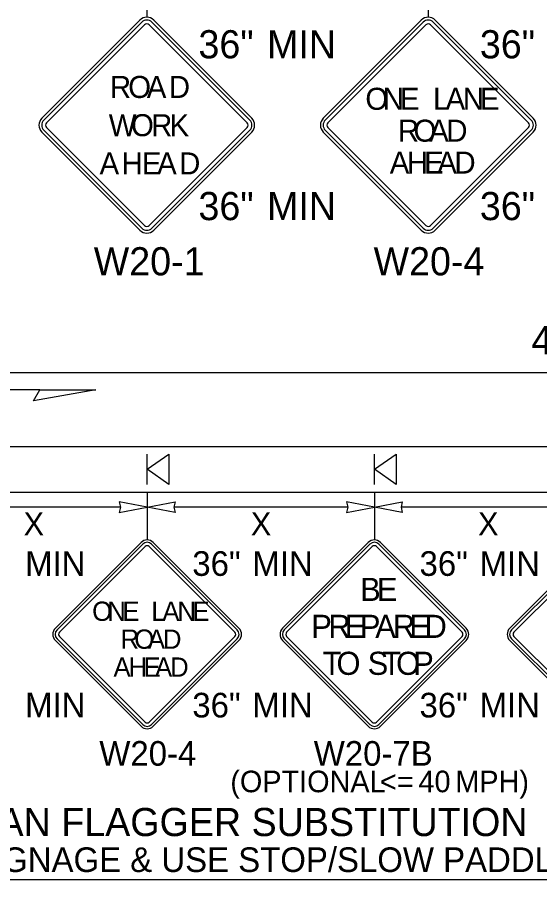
# Model space of a CAD drawing. Extents: x 99999.1 to 100095.7, y 99995 to 100010.7.
# Drawn here: x 100040.708 to 100042.194, y 100003.042 to 100005.492 of the extents above; entities that cross this region are included whole.
import ezdxf

# ---------------------------------------------------------------- set-up
doc = ezdxf.new("R2010")
doc.units = 0
for name, color, linetype in [('RD_ED_ShoulderPavedEdge', 7, 'Continuous'), ('RD_MK_LineEdgeWhite', 7, 'Continuous'), ('SH_DE_DetailHeading2Text', 7, 'Continuous'), ('TR_SN_ConstructionSigns', 7, 'Continuous'), ('TR_WZ_PortableSignMountBlk-Org', 7, 'Continuous'), ('TR_WZ_WorkZoneDetails', 7, 'Continuous'), ('TR_WZ_WorkZoneTextCurrent', 7, 'Continuous')]:
    doc.layers.add(name, color=color, linetype=linetype)

msp = doc.modelspace()

# ---------------------------------------------------------------- linework, layer by layer
at = {"layer": 'RD_ED_ShoulderPavedEdge'}
msp.add_line((100040.2089, 100004.1438), (100043.1825, 100004.1438), dxfattribs=at)
at = {"layer": 'RD_MK_LineEdgeWhite'}
msp.add_line((100040.2089, 100004.273), (100043.1825, 100004.273), dxfattribs=at)
at = {"layer": 'TR_SN_ConstructionSigns'}
for p, q in [((100041.0568, 100005.4841), (100040.7783, 100005.2057)), ((100041.0623, 100005.4786), (100040.7839, 100005.2001)), ((100040.7916, 100005.1924), (100041.07, 100005.4708)), ((100041.0833, 100005.4708), (100041.3617, 100005.1924)), ((100041.3694, 100005.2001), (100041.091, 100005.4786)), ((100041.375, 100005.2057), (100041.0965, 100005.4841)), ((100041.8568, 100005.4841), (100041.5783, 100005.2057)), ((100041.8623, 100005.4786), (100041.5839, 100005.2001)), ((100041.5916, 100005.1924), (100041.87, 100005.4708)), ((100041.8833, 100005.4708), (100042.1617, 100005.1924)), ((100042.1694, 100005.2001), (100041.891, 100005.4786)), ((100042.175, 100005.2057), (100041.8965, 100005.4841)), ((100040.7839, 100005.1714), (100041.0623, 100004.893)), ((100041.07, 100004.9007), (100040.7916, 100005.1792)), ((100041.3617, 100005.1792), (100041.0833, 100004.9007)), ((100041.091, 100004.893), (100041.3694, 100005.1714)), ((100041.5839, 100005.1714), (100041.8623, 100004.893)), ((100041.87, 100004.9007), (100041.5916, 100005.1792)), ((100042.1617, 100005.1792), (100041.8833, 100004.9007)), ((100041.891, 100004.893), (100042.1694, 100005.1714)), ((100040.7783, 100005.1659), (100041.0568, 100004.8875)), ((100041.0965, 100004.8875), (100041.375, 100005.1659)), ((100041.5783, 100005.1659), (100041.8568, 100004.8875)), ((100041.8965, 100004.8875), (100042.175, 100005.1659)), ((100041.0602, 100004.0005), (100040.8166, 100003.7569)), ((100041.065, 100003.9957), (100040.8214, 100003.752)), ((100041.3338, 100003.752), (100041.0902, 100003.9957)), ((100041.3386, 100003.7569), (100041.095, 100004.0005)), ((100041.7061, 100004.0005), (100041.4625, 100003.7569)), ((100041.711, 100003.9957), (100041.4673, 100003.752)), ((100041.9797, 100003.752), (100041.7361, 100003.9957)), ((100041.9846, 100003.7569), (100041.7409, 100004.0005)), ((100042.3521, 100004.0005), (100042.1084, 100003.7569)), ((100042.3569, 100003.9957), (100042.1133, 100003.752)), ((100040.8282, 100003.7453), (100041.0718, 100003.9889)), ((100041.0834, 100003.9889), (100041.327, 100003.7453)), ((100041.4741, 100003.7453), (100041.7177, 100003.9889)), ((100041.7293, 100003.9889), (100041.973, 100003.7453)), ((100042.12, 100003.7453), (100042.3637, 100003.9889)), ((100040.8214, 100003.7269), (100041.065, 100003.4833)), ((100041.0718, 100003.4901), (100040.8282, 100003.7337)), ((100041.327, 100003.7337), (100041.0834, 100003.4901)), ((100041.0902, 100003.4833), (100041.3338, 100003.7269)), ((100041.4673, 100003.7269), (100041.711, 100003.4833)), ((100041.7177, 100003.4901), (100041.4741, 100003.7337)), ((100041.973, 100003.7337), (100041.7293, 100003.4901)), ((100041.7361, 100003.4833), (100041.9797, 100003.7269)), ((100042.1133, 100003.7269), (100042.3569, 100003.4833)), ((100042.3637, 100003.4901), (100042.12, 100003.7337)), ((100040.8166, 100003.7221), (100041.0602, 100003.4785)), ((100041.095, 100003.4785), (100041.3386, 100003.7221)), ((100041.4625, 100003.7221), (100041.7061, 100003.4785)), ((100041.7409, 100003.4785), (100041.9846, 100003.7221)), ((100042.1084, 100003.7221), (100042.3521, 100003.4785))]:
    msp.add_line(p, q, dxfattribs=at)
for centre, radius, start, end in [((100041.0767, 100005.4642), 0.0281, 45, 135), ((100041.8767, 100005.4642), 0.0281, 45, 135), ((100041.0767, 100005.4642), 0.0203, 45, 135), ((100041.0767, 100005.4642), 0.00937, 45, 135), ((100041.8767, 100005.4642), 0.0203, 45, 135), ((100041.8767, 100005.4642), 0.00937, 45, 135), ((100040.7982, 100005.1858), 0.0281, 135, 225), ((100040.7982, 100005.1858), 0.0203, 135, 225), ((100041.3551, 100005.1858), 0.0203, 315, 45), ((100041.3551, 100005.1858), 0.0281, 315, 45), ((100041.5982, 100005.1858), 0.0281, 135, 225), ((100041.5982, 100005.1858), 0.0203, 135, 225), ((100042.1551, 100005.1858), 0.0203, 315, 45), ((100042.1551, 100005.1858), 0.0281, 315, 45), ((100040.7982, 100005.1858), 0.00937, 135, 225), ((100041.3551, 100005.1858), 0.00937, 315, 45), ((100041.5982, 100005.1858), 0.00937, 135, 225), ((100042.1551, 100005.1858), 0.00937, 315, 45), ((100041.0767, 100004.9074), 0.00937, 225, 315), ((100041.8767, 100004.9074), 0.00937, 225, 315), ((100041.0767, 100004.9074), 0.0281, 225, 315), ((100041.0767, 100004.9074), 0.0203, 225, 315), ((100041.8767, 100004.9074), 0.0281, 225, 315), ((100041.8767, 100004.9074), 0.0203, 225, 315), ((100041.0776, 100003.9831), 0.0246, 45, 135), ((100041.0776, 100003.9831), 0.0178, 45, 135), ((100041.7235, 100003.9831), 0.0246, 45, 135), ((100041.7235, 100003.9831), 0.0178, 45, 135), ((100041.0776, 100003.9831), 0.0082, 45, 135), ((100041.7235, 100003.9831), 0.0082, 45, 135), ((100040.834, 100003.7395), 0.0246, 135, 225), ((100040.834, 100003.7395), 0.0178, 135, 225), ((100041.3212, 100003.7395), 0.0178, 315, 45), ((100041.3212, 100003.7395), 0.0246, 315, 45), ((100041.4799, 100003.7395), 0.0246, 135, 225), ((100041.4799, 100003.7395), 0.0178, 135, 225), ((100041.9672, 100003.7395), 0.0178, 315, 45), ((100041.9672, 100003.7395), 0.0246, 315, 45), ((100042.1258, 100003.7395), 0.0246, 135, 225), ((100042.1258, 100003.7395), 0.0178, 135, 225), ((100040.834, 100003.7395), 0.0082, 135, 225), ((100041.3212, 100003.7395), 0.0082, 315, 45), ((100041.4799, 100003.7395), 0.0082, 135, 225), ((100041.9672, 100003.7395), 0.0082, 315, 45), ((100042.1258, 100003.7395), 0.0082, 135, 225), ((100041.0776, 100003.4959), 0.0246, 225, 315), ((100041.0776, 100003.4959), 0.0178, 225, 315), ((100041.0776, 100003.4959), 0.0082, 225, 315), ((100041.7235, 100003.4959), 0.0246, 225, 315), ((100041.7235, 100003.4959), 0.0178, 225, 315), ((100041.7235, 100003.4959), 0.0082, 225, 315)]:
    msp.add_arc(centre, radius, start, end, dxfattribs=at)
at = {"layer": 'TR_WZ_PortableSignMountBlk-Org'}
for p, q in [((100041.0776, 100004.1654), (100041.0776, 100004.2515)), ((100041.7235, 100004.1654), (100041.7235, 100004.2515))]:
    msp.add_line(p, q, dxfattribs=at)
for points in [[(100041.0776, 100004.2084), (100041.1395, 100004.2515), (100041.1395, 100004.1654)], [(100041.7235, 100004.2084), (100041.7854, 100004.2515), (100041.7854, 100004.1654)]]:
    msp.add_lwpolyline(points, close=True, dxfattribs=at)
at = {"layer": 'TR_WZ_WorkZoneDetails'}
for p, q in [((100041.0767, 100005.7326), (100041.0767, 100005.4923)), ((100041.8767, 100005.7323), (100041.8767, 100005.4923)), ((100040.7726, 100004.4337), (100040.578, 100004.4337)), ((100041.0776, 100004.1438), (100041.0776, 100004.0077)), ((100041.7235, 100004.1438), (100041.7235, 100004.0077)), ((100041.0019, 100004.1008), (100040.5073, 100004.1008)), ((100041.6479, 100004.1008), (100041.1533, 100004.1008)), ((100042.2938, 100004.1008), (100041.7992, 100004.1008))]:
    msp.add_line(p, q, dxfattribs=at)
for points in [[(100040.9313, 100004.4337), (100040.7546, 100004.4026), (100040.7726, 100004.4337)], [(100041.0776, 100004.1008), (100040.9982, 100004.1163), (100041.0019, 100004.1008), (100040.9982, 100004.0852)], [(100041.0776, 100004.1008), (100041.157, 100004.1163), (100041.1533, 100004.1008), (100041.157, 100004.0852)], [(100041.7235, 100004.1008), (100041.6442, 100004.1163), (100041.6479, 100004.1008), (100041.6442, 100004.0852)], [(100041.7235, 100004.1008), (100041.8029, 100004.1163), (100041.7992, 100004.1008), (100041.8029, 100004.0852)]]:
    msp.add_lwpolyline(points, close=True, dxfattribs=at)
at = {"layer": 'TR_WZ_WorkZoneTextCurrent'}
msp.add_lwpolyline([(100040.1, 100004.4837), (100043.2886, 100004.4837), (100043.2886, 100003.0424), (100040.1, 100003.0424)], close=True, dxfattribs=at)

# ---------------------------------------------------------------- texts
at = {"layer": 'SH_DE_DetailHeading2Text'}
msp.add_text('HUMAN FLAGGER SUBSTITUTION', height=0.08, rotation=360, dxfattribs=at).set_placement((100040.4115, 100003.1664))
at = {"layer": 'TR_SN_ConstructionSigns'}
for s, height, p in [('36"', 0.08, (100041.2234, 100005.3756)), ('MIN', 0.08, (100041.4184, 100005.3756)), ('36"', 0.08, (100042.0234, 100005.3756)), ('36"', 0.08, (100041.2234, 100004.916)), ('36"', 0.08, (100042.0234, 100004.916)), ('MIN', 0.08, (100041.4184, 100004.916)), ('W20-1', 0.08, (100040.9257, 100004.7592)), ('W20-4', 0.08, (100041.7212, 100004.7592)), ('40 MPH OR LESS', 0.08, (100042.1702, 100004.5352)), ('MIN', 0.07, (100040.7307, 100003.9056)), ('36"', 0.07, (100041.206, 100003.9056)), ('MIN', 0.07, (100041.3767, 100003.9056)), ('36"', 0.07, (100041.8519, 100003.9056)), ('MIN', 0.07, (100042.0226, 100003.9056)), ('MIN', 0.07, (100040.7307, 100003.5034)), ('36"', 0.07, (100041.206, 100003.5034)), ('MIN', 0.07, (100041.3767, 100003.5034)), ('36"', 0.07, (100041.8519, 100003.5034)), ('MIN', 0.07, (100042.0226, 100003.5034)), ('W20-4', 0.07, (100040.9416, 100003.3663)), ('W20-7B', 0.07, (100041.5512, 100003.3663)), ('(OPTIONAL', 0.06125, (100041.314, 100003.291)), ('MPH)', 0.06125, (100041.9536, 100003.291)), ('<=', 0.06125, (100041.7395, 100003.291)), ('40', 0.06125, (100041.8489, 100003.291))]:
    msp.add_text(s, height=height, rotation=360, dxfattribs=at).set_placement(p)
for s, height, p in [('R', 0.0625, (100040.9716, 100005.2631)), ('O', 0.0625, (100041.0237, 100005.2631)), ('A', 0.0625, (100041.0765, 100005.2631)), ('D', 0.0625, (100041.1392, 100005.2631)), ('O', 0.0625, (100041.6979, 100005.2295)), ('N', 0.0625, (100041.7473, 100005.2295)), ('E', 0.0625, (100041.796, 100005.2295)), ('L', 0.0625, (100041.8904, 100005.2295)), ('A', 0.0625, (100041.926, 100005.2295)), ('N', 0.0625, (100041.9748, 100005.2295)), ('E', 0.0625, (100042.0235, 100005.2295)), ('O', 0.0625, (100041.0316, 100005.1545)), ('W', 0.0625, (100040.9683, 100005.1545)), ('R', 0.0625, (100041.0888, 100005.1545)), ('K', 0.0625, (100041.1412, 100005.1545)), ('R', 0.0625, (100041.7904, 100005.1389)), ('O', 0.0625, (100041.8348, 100005.1389)), ('A', 0.0625, (100041.8792, 100005.1389)), ('D', 0.0625, (100041.9279, 100005.1389)), ('A', 0.0625, (100040.9423, 100005.046)), ('H', 0.0625, (100041.0048, 100005.046)), ('E', 0.0625, (100041.0623, 100005.046)), ('A', 0.0625, (100041.106, 100005.046)), ('D', 0.0625, (100041.1685, 100005.046)), ('A', 0.0625, (100041.7673, 100005.0483)), ('H', 0.0625, (100041.816, 100005.0483)), ('E', 0.0625, (100041.8648, 100005.0483)), ('A', 0.0625, (100041.9023, 100005.0483)), ('D', 0.0625, (100041.951, 100005.0483)), ('B', 0.0656, (100041.683, 100003.8344)), ('E', 0.0656, (100041.7306, 100003.8344)), ('O', 0.0547, (100040.9212, 100003.7778)), ('N', 0.0547, (100040.9644, 100003.7778)), ('E', 0.0547, (100041.0071, 100003.7778)), ('L', 0.0547, (100041.0896, 100003.7778)), ('A', 0.0547, (100041.1208, 100003.7778)), ('N', 0.0547, (100041.1635, 100003.7778)), ('E', 0.0547, (100041.2061, 100003.7778)), ('P', 0.0656, (100041.5442, 100003.7294)), ('R', 0.0656, (100041.5926, 100003.7294)), ('E', 0.0656, (100041.6391, 100003.7294)), ('P', 0.0656, (100041.6824, 100003.7294)), ('A', 0.0656, (100041.7261, 100003.7294)), ('R', 0.0656, (100041.7762, 100003.7294)), ('E', 0.0656, (100041.8228, 100003.7294)), ('D', 0.0656, (100041.8661, 100003.7294)), ('R', 0.0547, (100041.0021, 100003.6985)), ('O', 0.0547, (100041.041, 100003.6985)), ('A', 0.0547, (100041.0798, 100003.6985)), ('D', 0.0547, (100041.1224, 100003.6985)), ('A', 0.0547, (100040.9819, 100003.6192)), ('H', 0.0547, (100041.0246, 100003.6192)), ('E', 0.0547, (100041.0672, 100003.6192)), ('A', 0.0547, (100041.1, 100003.6192)), ('D', 0.0547, (100041.1427, 100003.6192)), ('T', 0.0656, (100041.5763, 100003.6244)), ('O', 0.0656, (100041.6158, 100003.6244)), ('S', 0.0656, (100041.7045, 100003.6244)), ('T', 0.0656, (100041.7458, 100003.6244)), ('O', 0.0656, (100041.7853, 100003.6244)), ('P', 0.0656, (100041.834, 100003.6244))]:
    msp.add_text(s, height=height, dxfattribs=at).set_placement(p)
at = {"layer": 'TR_WZ_WorkZoneTextCurrent'}
for s, height, p in [('X', 0.0646, (100040.7266, 100004.0211)), ('X', 0.0646, (100041.3725, 100004.0211)), ('X', 0.0646, (100042.0185, 100004.0211)), ('UPDATE SIGNAGE & USE STOP/SLOW PADDLE', 0.07, (100040.1713, 100003.0644))]:
    msp.add_text(s, height=height, dxfattribs=at).set_placement(p)

doc.saveas('drawing.dxf')
